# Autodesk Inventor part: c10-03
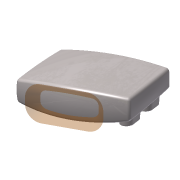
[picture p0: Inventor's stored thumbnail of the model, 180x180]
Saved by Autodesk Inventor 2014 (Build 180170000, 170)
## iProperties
Created: 2010-12
Part Number: c10-03
Material: Generic
Document SubType Name: Modeling
Designer: Thom Tremblay
Density: 1 g/cm^3
Appearance: Light Gray
Author: Thom Tremblay
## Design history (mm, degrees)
sketch "Sketch1"
  geometry: L1 (-60, -12)-(60, -12); L2 (60, -12)-(60, 12); L3 (60, 12)-(-60, 12); L4 (-60, 12)-(-60, -12); A1 r 350 centre (0, -332.819) between (60, 12) and (-60, 12); A2 r 350 centre (0, 332.819) between (-60, -12) and (60, -12); 3 further points
  constraints: 8 end point, 4 point on circle, 2 centre point, 2 midpoint, 2 parallel, 1 equal radius, 1 horizontal, 1 horizontal alignment, 1 perpendicular, 1 vertical alignment
  dimensions: "d0" = 120 distance of L3.end L2.end; "d1" = 24 distance of L2.end L1.end; "d2" = 350 radius of A1
workplane "Work Plane4"
sketch "Sketch5"
  geometry: L1 (-60, 12)-(-60, -12) reference; L2 (60, -12)-(60, 12) reference; L3 (-58, 10.314)-(-58, -10.314); L4 (58, -10.314)-(58, 10.314); A1 r 350 centre (0, 332.819) between (-60, -12) and (60, -12) reference; A2 r 350 centre (0, -332.819) between (60, 12) and (-60, 12) reference; A3 r 348 centre (0, 332.819) between (-58, -10.314) and (58, -10.314); A4 r 348 centre (0, -332.819) between (58, 10.314) and (-58, 10.314); 1 further point
  constraints: 4 end point, 4 point on circle, 2 centre point, 3 other
  dimensions: "d37" = 2 distance between parallel lines of L2 L4
sketch "Sketch6"
  geometry: L1 (-60, 0)-(60, 0); L2 (60, 0)-(58.843, 22.085); L3 (-60, 0)-(-58.779, 23.307); A1 r 691.758 centre (630.81, -36.204) between (-60, 0) and (-58, -100); A2 r 691.758 centre (-630.81, -36.204) between (58, -100) and (60, 0); 1 further point
  constraints: 6 end point, 4 point on circle, 2 centre point, 2 tangent, 1 horizontal
  dimensions: "d53" = 87 deg angle of L1 L3; "d54" = 87 deg angle of L1 L2 (= d53)
sketch "Sketch7"
  geometry: L1 (17.181, 0)-(12, 0) reference; L2 (15.181, -100)-(10.314, -100) reference; L3 (17.181, 0)-(16.768, 11.838); A1 r 911.322 centre (-893.585, -31.805) between (15.181, -100) and (17.181, 0); 1 further point
  constraints: 2 end point, 2 point on circle, 1 centre point, 1 tangent
  dimensions: "d56" = 88 deg angle of L1 L3
feature "LoftSrf2" sketch "Sketch5", "Sketch6", "Sketch7" dims "d57" = 0, "d58" = 90 deg, "d59" = 0, "d60" = 90 deg, "d61" = 0, "d62" = 90 deg, "d63" = 0, "d64" = 90 deg, "d65" = 0, "d66" = 90 deg
sketch "Sketch2"
  geometry: L1 (-75, -16)-(75, -16); L2 (-75, -60)-(75, -60); A1 r 183.781 centre (0, -183.781) between (75, -16) and (-75, -16); 2 further points
  constraints: 4 end point, 3 point on circle, 1 centre point, 1 coincident, 1 horizontal, 1 parallel
  dimensions: "d5" = 16 distance from line of point (0, 0) L1; "d7" = 60 distance from line of point (0, 0) L2; "d55" = 150 distance of L1.start L1.end
feature "RevolutionSrf1" sketch "Sketch2" dims angle "d8" = 40 deg
patch "Boundary Patch1" dims "d13" = 0, "d67" = 0, "d68" = 0, "d69" = 0, "d70" = 0
workplane "Work Plane1"
sketch "Sketch3"
  geometry: L1 (52, -85)-(52, -73); L2 (38, -73)-(38, -85); A1 r 7 centre (45, -73) between (52, -73) and (38, -73); A2 r 7 centre (45, -85) between (38, -85) and (52, -85); 1 further point
  constraints: 4 end point, 4 point on circle, 4 tangent, 2 centre point, 1 parallel, 1 vertical
  dimensions: "d15" = 12 distance of L1.start L1.end; "d16" = 7 radius of A1; "d50" = 45 horizontal distance of A1.centre point (0, 0); "d51" = 85 vertical distance of point (0, 0) A2.centre
extrude_surface "ExtrusionSrf2" sketch "Sketch3" dims "d19" = 14, "d20" = 5 deg
pattern_linear "Rectangular Pattern1" dims "d23" = 90
workplane "Work Plane2"
feature "Sculpt1"
sketch "Sketch4"
  geometry: L1 (-24.5, 6)-(24.5, 6); L2 (27.5, 3)-(27.5, -3); L3 (24.5, -6)-(-24.5, -6); L4 (-27.5, -3)-(-27.5, 3); A1 r 3 centre (-24.5, 3) between (-24.5, 6) and (-27.5, 3); A2 r 3 centre (24.5, 3) between (27.5, 3) and (24.5, 6); A3 r 3 centre (24.5, -3) between (24.5, -6) and (27.5, -3); A4 r 3 centre (-24.5, -3) between (-27.5, -3) and (-24.5, -6); 6 further points
  constraints: 8 end point, 8 point on circle, 8 tangent, 6 point on line, 4 centre point, 3 equal radius, 2 midpoint, 2 parallel, 1 horizontal, 1 horizontal alignment, 1 perpendicular, 1 vertical alignment
  dimensions: "d28" = 55 distance of point (27.5, -6) point (-27.5, -6); "d29" = 12 distance of point (27.5, 6) point (27.5, -6); "d30" = 3 radius of A1
extrude_surface "ExtrusionSrf6" sketch "Sketch4" dims "d31" = 14, "d32" = 45 deg
patch "Boundary Patch2" dims "d33" = 0, "d34" = 0
fillet "Fillet1" dims "d79" = 4, "d80" = 3, "d81" = 1
body "Solid1"
body "Srf2"
body "Srf3"
body "Srf4"
body "Srf5"
body "Srf6"
body "Srf7"
body "Srf8"
body "Srf9"
body "Srf11"
extrude_surface "ExtrusionSrf3"
extrude_surface "ExtrusionSrf4"
extrude_surface "ExtrusionSrf5"
other parameters: "d14" = -24, "d52" = -6
